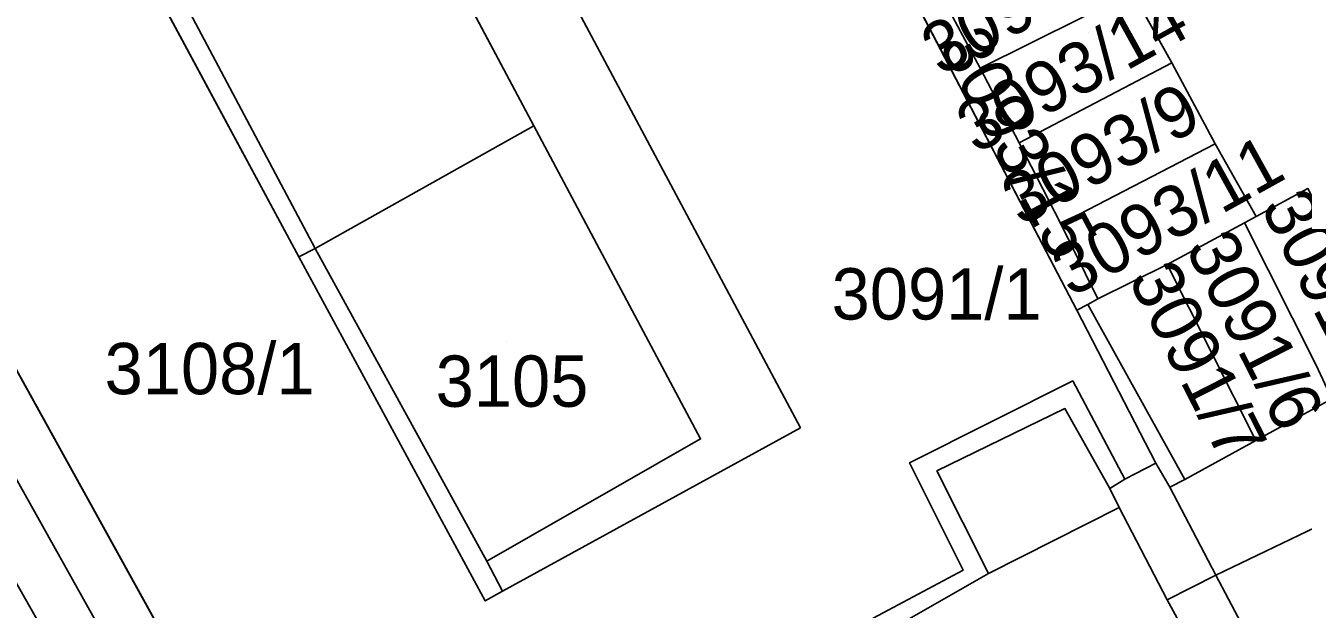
# Model space of a CAD drawing. Extents: x -264070 to -262271, y -1238894 to -1238141.
# Drawn here: x -263118.51 to -263068.73, y -1238411.21 to -1238388.46 of the extents above; entities that cross this region are included whole.
import ezdxf

# ---------------------------------------------------------------- set-up
doc = ezdxf.new("R2010")
doc.units = 0
for name, color, linetype in [('body_kn', 7, 'Continuous'), ('kladpar_druhypozemkov', 7, 'Continuous'), ('kladpar_hranice', 7, 'Continuous'), ('kladpar_parcelnecisla', 7, 'Continuous'), ('kladpar_plochy', 7, 'Continuous'), ('kladpar_sipky', 7, 'Continuous'), ('zappar_hrandruhpozemk', 7, 'Continuous')]:
    doc.layers.add(name, color=color, linetype=linetype)

msp = doc.modelspace()

# ---------------------------------------------------------------- linework, layer by layer
at = {"layer": 'body_kn'}
for p, q in [((-263073.86, -1238389.91), (-263073.86, -1238389.91)), ((-263073.86, -1238389.91), (-263073.86, -1238389.91)), ((-263081.33, -1238390.12), (-263081.33, -1238390.12)), ((-263081.33, -1238390.12), (-263081.33, -1238390.12)), ((-263098.71, -1238392.36), (-263098.71, -1238392.36)), ((-263098.71, -1238392.36), (-263098.71, -1238392.36)), ((-263079.81, -1238393.03), (-263079.81, -1238393.03)), ((-263072.18, -1238393.07), (-263072.18, -1238393.07)), ((-263072.18, -1238393.07), (-263072.18, -1238393.07)), ((-263070.58, -1238395.89), (-263070.58, -1238395.89)), ((-263078.19, -1238396.18), (-263078.19, -1238396.18)), ((-263071.03, -1238396.14), (-263071.03, -1238396.14)), ((-263071.03, -1238396.14), (-263071.03, -1238396.14)), ((-263107.23, -1238397.14), (-263107.23, -1238397.14)), ((-263107.23, -1238397.14), (-263107.23, -1238397.14)), ((-263107.87, -1238397.47), (-263107.87, -1238397.47)), ((-263074.04, -1238397.77), (-263074.04, -1238397.77)), ((-263077.14, -1238399.33), (-263077.14, -1238399.33)), ((-263076.74, -1238399.11), (-263076.74, -1238399.11)), ((-263077.56, -1238399.55), (-263077.56, -1238399.55)), ((-263077.72, -1238402.3), (-263077.72, -1238402.3)), ((-263078.03, -1238403.38), (-263078.03, -1238403.38)), ((-263088.33, -1238404.13), (-263088.33, -1238404.13)), ((-263092.22, -1238404.56), (-263092.22, -1238404.56)), ((-263070.59, -1238404.62), (-263070.59, -1238404.62)), ((-263070.59, -1238404.62), (-263070.59, -1238404.62)), ((-263084.08, -1238405.49), (-263084.08, -1238405.49)), ((-263083.01, -1238405.81), (-263083.01, -1238405.81)), ((-263074.48, -1238405.5), (-263074.48, -1238405.5)), ((-263075.69, -1238406.13), (-263075.69, -1238406.13)), ((-263073.36, -1238406.14), (-263073.36, -1238406.14)), ((-263073.36, -1238406.14), (-263073.36, -1238406.14)), ((-263076.28, -1238406.49), (-263076.28, -1238406.49)), ((-263076.28, -1238406.49), (-263076.28, -1238406.49)), ((-263073.94, -1238406.44), (-263073.94, -1238406.44)), ((-263073.94, -1238406.44), (-263073.94, -1238406.44)), ((-263075.91, -1238407.23), (-263075.91, -1238407.23)), ((-263075.91, -1238407.23), (-263075.91, -1238407.23)), ((-263100.54, -1238409.32), (-263100.54, -1238409.32)), ((-263100.54, -1238409.32), (-263100.54, -1238409.32)), ((-263081.99, -1238409.67), (-263081.99, -1238409.67)), ((-263081.01, -1238409.81), (-263081.01, -1238409.81)), ((-263081.01, -1238409.81), (-263081.01, -1238409.81)), ((-263072.15, -1238409.87), (-263072.15, -1238409.87)), ((-263072.15, -1238409.87), (-263072.15, -1238409.87)), ((-263100.61, -1238410.87), (-263100.61, -1238410.87)), ((-263099.94, -1238410.49), (-263099.94, -1238410.49)), ((-263074.05, -1238410.83), (-263074.05, -1238410.83)), ((-263074.05, -1238410.83), (-263074.05, -1238410.83))]:
    msp.add_line(p, q, dxfattribs=at)
at = {"layer": 'kladpar_druhypozemkov'}
for p, q in [((-263077.1, -1238388.72), (-263077.1, -1238388.72)), ((-263082.75, -1238389.07), (-263082.75, -1238389.07)), ((-263075.39, -1238391.43), (-263075.39, -1238391.43)), ((-263073.97, -1238394.64), (-263073.97, -1238394.64)), ((-263111.23, -1238400.8), (-263111.23, -1238400.8)), ((-263099.77, -1238400.75), (-263099.77, -1238400.75)), ((-263069.87, -1238401), (-263069.87, -1238401)), ((-263075.99, -1238402.17), (-263075.99, -1238402.17)), ((-263072.37, -1238402.4), (-263072.37, -1238402.4))]:
    msp.add_line(p, q, dxfattribs=at)
at = {"layer": 'kladpar_hranice'}
for points in [[(-263068.56, -1238394.81), (-263070.58, -1238395.89), (-263072.18, -1238393.07), (-263073.86, -1238389.91), (-263075.4, -1238387.15), (-263077.04, -1238384.18), (-263078.54, -1238381.47), (-263080.18, -1238378.46), (-263077.39, -1238376.88), (-263078.98, -1238374.05), (-263080.16, -1238371.88), (-263081.58, -1238369.17), (-263082.82, -1238366.87), (-263084.23, -1238364.27), (-263085.74, -1238361.49), (-263080.9, -1238358.55), (-263079.65, -1238357.85), (-263045.28, -1238338.72)], [(-263116.28, -1238369.42), (-263098.65, -1238360.02), (-263098.34, -1238360.6), (-263099.48, -1238361.14), (-263102.27, -1238362.64), (-263105.65, -1238364.29), (-263109.27, -1238366.16), (-263112.99, -1238368.21), (-263115.9, -1238369.92), (-263111.81, -1238377.15), (-263094.25, -1238367.7), (-263086.85, -1238381.84), (-263085.96, -1238383.47), (-263077.56, -1238399.55), (-263074.48, -1238405.5), (-263075.69, -1238406.13), (-263077.72, -1238402.3), (-263084.08, -1238405.49), (-263081.99, -1238409.67), (-263085.49, -1238411.54)], [(-263100.61, -1238410.87), (-263099.94, -1238410.49), (-263100.54, -1238409.32), (-263092.22, -1238404.56), (-263098.71, -1238392.36), (-263105.48, -1238379.65), (-263110.8, -1238382.48), (-263111.6, -1238382.91), (-263114.05, -1238384.29), (-263115.82, -1238381.08), (-263116.47, -1238381.47), (-263107.87, -1238397.47), (-263100.61, -1238410.87)], [(-263098.71, -1238392.36), (-263107.23, -1238397.14), (-263107.87, -1238397.47), (-263116.47, -1238381.47), (-263115.82, -1238381.08), (-263114.05, -1238384.29), (-263111.6, -1238382.91), (-263110.8, -1238382.48), (-263105.48, -1238379.65), (-263098.71, -1238392.36)], [(-263081.33, -1238390.12), (-263079.81, -1238393.03), (-263078.19, -1238396.18), (-263076.74, -1238399.11), (-263077.14, -1238399.33), (-263077.56, -1238399.55), (-263085.96, -1238383.47), (-263085.07, -1238383), (-263084.34, -1238384.4), (-263082.79, -1238387.36), (-263081.33, -1238390.12)], [(-263077.04, -1238384.18), (-263075.4, -1238387.15), (-263081.33, -1238390.12), (-263082.79, -1238387.36), (-263077.04, -1238384.18)], [(-263075.4, -1238387.15), (-263073.86, -1238389.91), (-263079.81, -1238393.03), (-263081.33, -1238390.12), (-263075.4, -1238387.15)], [(-263073.86, -1238389.91), (-263072.18, -1238393.07), (-263078.19, -1238396.18), (-263079.81, -1238393.03), (-263073.86, -1238389.91)], [(-263125.27, -1238390.31), (-263107.07, -1238423.22), (-263105.74, -1238425.81), (-263106.9, -1238426.35), (-263109.29, -1238427.47), (-263115.06, -1238430.1), (-263116.05, -1238430.55), (-263118.32, -1238431.64), (-263118.71, -1238430.8)], [(-263107.07, -1238423.22), (-263125.27, -1238390.31)], [(-263098.71, -1238392.36), (-263092.22, -1238404.56), (-263100.54, -1238409.32), (-263099.94, -1238410.49), (-263100.61, -1238410.87), (-263107.87, -1238397.47), (-263107.23, -1238397.14), (-263098.71, -1238392.36)], [(-263072.18, -1238393.07), (-263070.58, -1238395.89), (-263071.03, -1238396.14), (-263074.04, -1238397.77), (-263076.74, -1238399.11), (-263078.19, -1238396.18), (-263072.18, -1238393.07)], [(-263065.75, -1238400.3), (-263065.09, -1238401.64), (-263067.63, -1238403), (-263068.25, -1238401.66), (-263071.03, -1238396.14), (-263070.58, -1238395.89), (-263068.56, -1238394.81), (-263065.75, -1238400.3)], [(-263071.03, -1238396.14), (-263068.25, -1238401.66), (-263067.63, -1238403), (-263070.59, -1238404.62), (-263074.04, -1238397.77), (-263071.03, -1238396.14)], [(-263070.59, -1238404.62), (-263073.36, -1238406.14), (-263077.14, -1238399.33), (-263076.74, -1238399.11), (-263074.04, -1238397.77), (-263070.59, -1238404.62)], [(-263069.38, -1238419.39), (-263074.05, -1238410.83), (-263075.91, -1238407.23), (-263076.28, -1238406.49), (-263075.69, -1238406.13), (-263074.48, -1238405.5), (-263073.94, -1238406.44), (-263073.36, -1238406.14), (-263070.59, -1238404.62), (-263067.63, -1238403), (-263065.09, -1238401.64), (-263062.47, -1238400.23), (-263059.82, -1238398.8)], [(-263073.36, -1238406.14), (-263073.94, -1238406.44), (-263074.48, -1238405.5), (-263077.56, -1238399.55), (-263077.14, -1238399.33), (-263073.36, -1238406.14)], [(-263075.91, -1238407.23), (-263074.05, -1238410.83), (-263069.38, -1238419.39), (-263077.67, -1238423.72), (-263078.47, -1238424.12), (-263083.68, -1238415.06), (-263085.49, -1238411.54), (-263081.99, -1238409.67), (-263084.08, -1238405.49), (-263077.72, -1238402.3), (-263075.69, -1238406.13), (-263076.28, -1238406.49), (-263075.91, -1238407.23)]]:
    msp.add_lwpolyline(points, dxfattribs=at)
at = {"layer": 'kladpar_plochy'}
for p, q in [((-263098.71, -1238392.36), (-263105.48, -1238379.65)), ((-263116.47, -1238381.47), (-263107.87, -1238397.47)), ((-263085.96, -1238383.47), (-263077.56, -1238399.55)), ((-263073.86, -1238389.91), (-263075.4, -1238387.15)), ((-263072.18, -1238393.07), (-263073.86, -1238389.91)), ((-263107.07, -1238423.22), (-263125.27, -1238390.31)), ((-263092.22, -1238404.56), (-263098.71, -1238392.36)), ((-263070.58, -1238395.89), (-263072.18, -1238393.07)), ((-263068.56, -1238394.81), (-263070.58, -1238395.89)), ((-263107.87, -1238397.47), (-263100.61, -1238410.87)), ((-263077.56, -1238399.55), (-263074.48, -1238405.5)), ((-263077.72, -1238402.3), (-263084.08, -1238405.49)), ((-263075.69, -1238406.13), (-263077.72, -1238402.3)), ((-263100.54, -1238409.32), (-263092.22, -1238404.56)), ((-263084.08, -1238405.49), (-263081.99, -1238409.67)), ((-263074.48, -1238405.5), (-263075.69, -1238406.13)), ((-263099.94, -1238410.49), (-263100.54, -1238409.32)), ((-263081.99, -1238409.67), (-263085.49, -1238411.54)), ((-263100.61, -1238410.87), (-263099.94, -1238410.49))]:
    msp.add_line(p, q, dxfattribs=at)
for points in [[(-263098.71, -1238392.36), (-263107.23, -1238397.14), (-263107.87, -1238397.47), (-263116.47, -1238381.47), (-263115.82, -1238381.08), (-263114.05, -1238384.29), (-263111.6, -1238382.91), (-263110.8, -1238382.48), (-263105.48, -1238379.65)], [(-263081.33, -1238390.12), (-263079.81, -1238393.03), (-263078.19, -1238396.18), (-263076.74, -1238399.11), (-263077.14, -1238399.33), (-263077.56, -1238399.55), (-263085.96, -1238383.47), (-263085.07, -1238383), (-263084.34, -1238384.4), (-263082.79, -1238387.36)], [(-263077.04, -1238384.18), (-263075.4, -1238387.15), (-263081.33, -1238390.12), (-263082.79, -1238387.36)], [(-263075.4, -1238387.15), (-263073.86, -1238389.91), (-263079.81, -1238393.03), (-263081.33, -1238390.12)], [(-263073.86, -1238389.91), (-263072.18, -1238393.07), (-263078.19, -1238396.18), (-263079.81, -1238393.03)], [(-263098.71, -1238392.36), (-263092.22, -1238404.56), (-263100.54, -1238409.32), (-263099.94, -1238410.49), (-263100.61, -1238410.87), (-263107.87, -1238397.47), (-263107.23, -1238397.14)], [(-263072.18, -1238393.07), (-263070.58, -1238395.89), (-263071.03, -1238396.14), (-263074.04, -1238397.77), (-263076.74, -1238399.11), (-263078.19, -1238396.18)], [(-263065.75, -1238400.3), (-263065.09, -1238401.64), (-263067.63, -1238403), (-263068.25, -1238401.66), (-263071.03, -1238396.14), (-263070.58, -1238395.89), (-263068.56, -1238394.81)], [(-263071.03, -1238396.14), (-263068.25, -1238401.66), (-263067.63, -1238403), (-263070.59, -1238404.62), (-263074.04, -1238397.77)], [(-263070.59, -1238404.62), (-263073.36, -1238406.14), (-263077.14, -1238399.33), (-263076.74, -1238399.11), (-263074.04, -1238397.77)], [(-263073.36, -1238406.14), (-263073.94, -1238406.44), (-263074.48, -1238405.5), (-263077.56, -1238399.55), (-263077.14, -1238399.33)], [(-263075.91, -1238407.23), (-263074.05, -1238410.83), (-263069.38, -1238419.39), (-263077.67, -1238423.72), (-263078.47, -1238424.12), (-263083.68, -1238415.06), (-263085.49, -1238411.54), (-263081.99, -1238409.67), (-263084.08, -1238405.49), (-263077.72, -1238402.3), (-263075.69, -1238406.13), (-263076.28, -1238406.49)]]:
    msp.add_lwpolyline(points, close=True, dxfattribs=at)
for points in [[(-263125.27, -1238390.31), (-263107.07, -1238423.22), (-263105.74, -1238425.81), (-263106.9, -1238426.35), (-263109.29, -1238427.47), (-263115.06, -1238430.1), (-263116.05, -1238430.55), (-263118.32, -1238431.64), (-263118.71, -1238430.8)], [(-263069.38, -1238419.39), (-263074.05, -1238410.83), (-263075.91, -1238407.23), (-263076.28, -1238406.49), (-263075.69, -1238406.13), (-263074.48, -1238405.5), (-263073.94, -1238406.44), (-263073.36, -1238406.14), (-263070.59, -1238404.62), (-263067.63, -1238403), (-263065.09, -1238401.64), (-263062.47, -1238400.23), (-263059.82, -1238398.8), (-263058.03, -1238397.92), (-263055.82, -1238402), (-263051.2, -1238410.54), (-263044.42, -1238423.03)]]:
    msp.add_lwpolyline(points, dxfattribs=at)
at = {"layer": 'kladpar_sipky'}
msp.add_line((-263077.02, -1238400.16), (-263077.02, -1238400.16), dxfattribs=at)
at = {"layer": 'zappar_hrandruhpozemk'}
for p, q in [((-263104.05, -1238374.63), (-263088.33, -1238404.13)), ((-263107.23, -1238397.14), (-263114.05, -1238384.29)), ((-263124.93, -1238395.33), (-263112.86, -1238416.86)), ((-263100.54, -1238409.32), (-263107.23, -1238397.14)), ((-263072.15, -1238409.87), (-263055.82, -1238402)), ((-263088.33, -1238404.13), (-263099.94, -1238410.49)), ((-263081.01, -1238409.81), (-263075.91, -1238407.23)), ((-263074.05, -1238410.83), (-263072.15, -1238409.87))]:
    msp.add_line(p, q, dxfattribs=at)
for points in [[(-263125, -1238399.4), (-263113.36, -1238419.9), (-263109.29, -1238427.47)], [(-263076.28, -1238406.49), (-263078.03, -1238403.38), (-263083.01, -1238405.81), (-263081.01, -1238409.81), (-263084.37, -1238411.73)], [(-263073.94, -1238406.44), (-263072.15, -1238409.87), (-263060.09, -1238432.72)]]:
    msp.add_lwpolyline(points, dxfattribs=at)

# ---------------------------------------------------------------- texts
at = {"layer": 'kladpar_parcelnecisla'}
for s, rotation, p in [('3093/10', 29, (-263082.862, -1238390.45)), ('3093/14', 29, (-263081.495, -1238393.485)), ('3093/15', 298, (-263082.985, -1238389.205)), ('3093/9', 29, (-263079.734, -1238396.31)), ('3093/11', 29, (-263077.787, -1238399.067)), ('3091/2', 297, (-263070.427, -1238395.521)), ('3091/6', 297, (-263073.358, -1238397.118)), ('3091/7', 297, (-263075.586, -1238398.32))]:
    msp.add_text(s, height=2, rotation=rotation, dxfattribs=at).set_placement(p)
for s, p in [('3091/1', (-263087.115, -1238399.91)), ('3108/1', (-263115.436, -1238402.82)), ('3105', (-263102.54, -1238403.31))]:
    msp.add_text(s, height=2, dxfattribs=at).set_placement(p)

doc.saveas('drawing.dxf')
